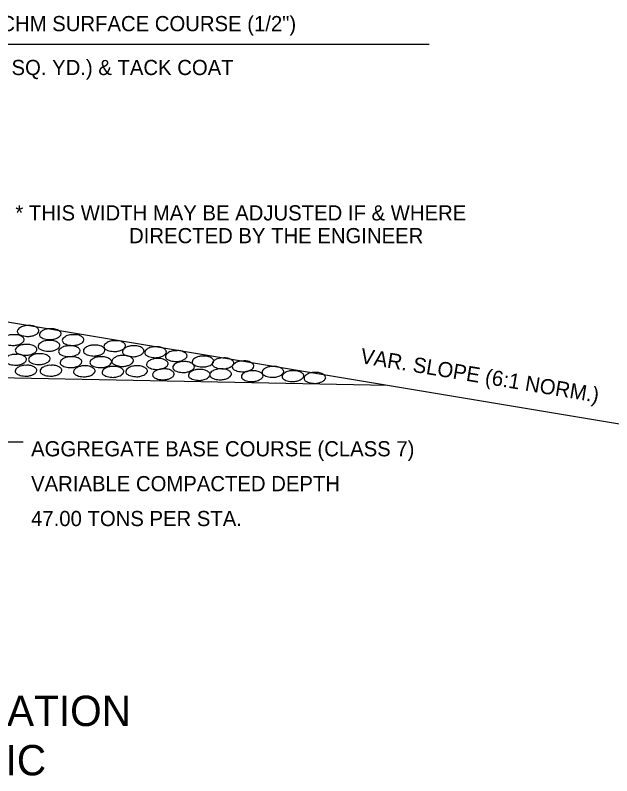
# Model space of a CAD drawing. Extents: x 1931522 to 1935523, y 600380 to 605075.
# Drawn here: x 1933516.8 to 1933752.7, y 604149.7 to 604450.3 of the extents above; entities that cross this region are included whole.
import ezdxf

# ---------------------------------------------------------------- set-up
doc = ezdxf.new("R2010")
doc.units = 0
doc.layers.add('Default', color=7, linetype='Continuous')
doc.layers.add('R_Border', color=7, linetype='Continuous')

msp = doc.modelspace()

# ---------------------------------------------------------------- linework, layer by layer
at = {"layer": 'Default'}
for p, q in [((1933680.47, 604438.7), (1933439.73, 604438.7)), ((1933439.73, 604341.45), (1933830.96, 604276.24)), ((1933261.14, 604312.09), (1933664.05, 604304.05))]:
    msp.add_line(p, q, dxfattribs=at)
for points in [[(1933521.88, 604327.61), (1933523.38, 604327.58), (1933525.22, 604326.96), (1933526.08, 604326.1), (1933526.22, 604325.59), (1933525.75, 604324.65), (1933525.23, 604324.25), (1933524.24, 604323.75), (1933522.77, 604323.41), (1933522.01, 604323.31), (1933520.9, 604323.44), (1933519.64, 604323.64), (1933518.69, 604324.03), (1933517.8, 604324.72), (1933517.66, 604325.32), (1933517.96, 604326.15), (1933518.64, 604326.69), (1933519.27, 604327.13), (1933520.26, 604327.43), (1933520.92, 604327.58), (1933521.88, 604327.61)], [(1933530.61, 604326.34), (1933532.12, 604326.32), (1933533.96, 604325.71), (1933534.85, 604324.84), (1933534.97, 604324.33), (1933534.49, 604323.41), (1933533.98, 604323), (1933533, 604322.52), (1933531.51, 604322.16), (1933530.75, 604322.07), (1933529.64, 604322.18), (1933528.43, 604322.38), (1933527.43, 604322.77), (1933526.58, 604323.47), (1933526.43, 604324.06), (1933526.72, 604324.89), (1933527.39, 604325.42), (1933528.02, 604325.87), (1933529.02, 604326.18), (1933529.66, 604326.32), (1933530.61, 604326.34)], [(1933515.99, 604324.03), (1933517.51, 604324), (1933519.34, 604323.39), (1933520.23, 604322.52), (1933520.36, 604322.02), (1933519.87, 604321.07), (1933519.36, 604320.68), (1933518.38, 604320.18), (1933516.9, 604319.84), (1933516.15, 604319.76), (1933515.03, 604319.85), (1933513.8, 604320.07), (1933512.83, 604320.45), (1933511.94, 604321.15), (1933511.82, 604321.74), (1933512.07, 604322.57), (1933512.77, 604323.1), (1933513.41, 604323.53), (1933514.4, 604323.87), (1933515.06, 604324), (1933515.99, 604324.03)], [(1933539.63, 604324.03), (1933541.13, 604324), (1933542.95, 604323.39), (1933543.87, 604322.52), (1933543.98, 604322.02), (1933543.53, 604321.07), (1933543, 604320.68), (1933542.02, 604320.18), (1933540.54, 604319.84), (1933539.77, 604319.76), (1933538.64, 604319.85), (1933537.41, 604320.07), (1933536.47, 604320.45), (1933535.6, 604321.15), (1933535.44, 604321.74), (1933535.71, 604322.57), (1933536.41, 604323.1), (1933537.03, 604323.53), (1933538.06, 604323.87), (1933538.7, 604324), (1933539.63, 604324.03)], [(1933521.07, 604320.18), (1933522.59, 604320.15), (1933524.39, 604319.54), (1933525.28, 604318.67), (1933525.42, 604318.2), (1933524.92, 604317.25), (1933524.41, 604316.85), (1933523.44, 604316.36), (1933521.95, 604315.99), (1933521.2, 604315.93), (1933520.09, 604316), (1933518.86, 604316.21), (1933517.9, 604316.6), (1933517.01, 604317.3), (1933516.85, 604317.91), (1933517.15, 604318.73), (1933517.83, 604319.29), (1933518.47, 604319.7), (1933519.45, 604320.01), (1933520.11, 604320.15), (1933521.07, 604320.18)], [(1933530.13, 604321.74), (1933531.64, 604321.72), (1933533.45, 604321.12), (1933534.35, 604320.26), (1933534.48, 604319.74), (1933533.99, 604318.78), (1933533.49, 604318.4), (1933532.51, 604317.91), (1933531.03, 604317.53), (1933530.27, 604317.47), (1933529.16, 604317.58), (1933527.92, 604317.78), (1933526.95, 604318.17), (1933526.06, 604318.86), (1933525.92, 604319.46), (1933526.2, 604320.29), (1933526.9, 604320.82), (1933527.53, 604321.24), (1933528.52, 604321.58), (1933529.18, 604321.72), (1933530.13, 604321.74)], [(1933556.12, 604321.65), (1933557.63, 604321.63), (1933559.46, 604321.01), (1933560.34, 604320.13), (1933560.48, 604319.64), (1933559.99, 604318.72), (1933559.47, 604318.28), (1933558.47, 604317.81), (1933556.99, 604317.45), (1933556.25, 604317.38), (1933555.14, 604317.47), (1933553.89, 604317.67), (1933552.94, 604318.06), (1933552.05, 604318.76), (1933551.91, 604319.36), (1933552.19, 604320.18), (1933552.86, 604320.73), (1933553.52, 604321.18), (1933554.52, 604321.49), (1933555.17, 604321.63), (1933556.12, 604321.65)], [(1933538.2, 604319.64), (1933539.73, 604319.6), (1933541.52, 604319), (1933542.42, 604318.11), (1933542.56, 604317.63), (1933542.08, 604316.69), (1933541.53, 604316.27), (1933540.58, 604315.8), (1933539.07, 604315.43), (1933538.34, 604315.37), (1933537.22, 604315.46), (1933536, 604315.69), (1933535.04, 604316.04), (1933534.15, 604316.75), (1933533.99, 604317.36), (1933534.27, 604318.2), (1933534.96, 604318.73), (1933535.61, 604319.15), (1933536.63, 604319.48), (1933537.23, 604319.6), (1933538.2, 604319.64)], [(1933547.97, 604319.87), (1933549.51, 604319.85), (1933551.32, 604319.23), (1933552.21, 604318.37), (1933552.32, 604317.86), (1933551.85, 604316.92), (1933551.34, 604316.52), (1933550.37, 604316.02), (1933548.87, 604315.69), (1933548.13, 604315.58), (1933547, 604315.71), (1933545.79, 604315.91), (1933544.82, 604316.27), (1933543.93, 604317), (1933543.78, 604317.59), (1933544.06, 604318.42), (1933544.74, 604318.95), (1933545.4, 604319.39), (1933546.38, 604319.7), (1933547.02, 604319.85), (1933547.97, 604319.87)], [(1933563.41, 604319.59), (1933564.92, 604319.57), (1933566.75, 604318.95), (1933567.64, 604318.08), (1933567.76, 604317.59), (1933567.28, 604316.66), (1933566.76, 604316.22), (1933565.78, 604315.76), (1933564.3, 604315.38), (1933563.55, 604315.33), (1933562.43, 604315.41), (1933561.2, 604315.63), (1933560.22, 604316), (1933559.35, 604316.71), (1933559.22, 604317.3), (1933559.49, 604318.11), (1933560.17, 604318.67), (1933560.83, 604319.12), (1933561.81, 604319.43), (1933562.45, 604319.57), (1933563.41, 604319.59)], [(1933572.23, 604319.18), (1933573.74, 604319.17), (1933575.57, 604318.56), (1933576.46, 604317.7), (1933576.6, 604317.2), (1933576.13, 604316.24), (1933575.58, 604315.83), (1933574.62, 604315.37), (1933573.15, 604315.01), (1933572.37, 604314.95), (1933571.27, 604315.02), (1933570.02, 604315.23), (1933569.07, 604315.63), (1933568.2, 604316.35), (1933568.04, 604316.92), (1933568.29, 604317.75), (1933569.01, 604318.28), (1933569.63, 604318.73), (1933570.66, 604319.04), (1933571.3, 604319.17), (1933572.23, 604319.18)], [(1933580.4, 604317.7), (1933581.91, 604317.69), (1933583.73, 604317.05), (1933584.65, 604316.19), (1933584.79, 604315.69), (1933584.29, 604314.76), (1933583.76, 604314.34), (1933582.8, 604313.85), (1933581.29, 604313.48), (1933580.55, 604313.43), (1933579.42, 604313.51), (1933578.2, 604313.73), (1933577.25, 604314.12), (1933576.36, 604314.82), (1933576.22, 604315.44), (1933576.49, 604316.22), (1933577.17, 604316.78), (1933577.83, 604317.22), (1933578.81, 604317.55), (1933579.43, 604317.69), (1933580.4, 604317.7)], [(1933516.93, 604316.25), (1933518.44, 604316.24), (1933520.26, 604315.6), (1933521.18, 604314.74), (1933521.32, 604314.24), (1933520.82, 604313.31), (1933520.3, 604312.89), (1933519.33, 604312.41), (1933517.82, 604312.03), (1933517.09, 604311.98), (1933515.95, 604312.06), (1933514.73, 604312.28), (1933513.78, 604312.67), (1933512.89, 604313.37), (1933512.75, 604313.99), (1933513.02, 604314.77), (1933513.7, 604315.33), (1933514.36, 604315.77), (1933515.34, 604316.1), (1933515.96, 604316.24), (1933516.93, 604316.25)], [(1933526.29, 604316.49), (1933527.81, 604316.47), (1933529.63, 604315.83), (1933530.55, 604314.98), (1933530.69, 604314.48), (1933530.19, 604313.54), (1933529.66, 604313.12), (1933528.69, 604312.64), (1933527.18, 604312.26), (1933526.45, 604312.22), (1933525.31, 604312.3), (1933524.1, 604312.51), (1933523.15, 604312.9), (1933522.26, 604313.61), (1933522.12, 604314.23), (1933522.38, 604315.01), (1933523.07, 604315.57), (1933523.72, 604316), (1933524.71, 604316.33), (1933525.33, 604316.47), (1933526.29, 604316.49)], [(1933538.79, 604315.29), (1933540.3, 604315.27), (1933542.13, 604314.63), (1933543.05, 604313.78), (1933543.19, 604313.28), (1933542.69, 604312.34), (1933542.16, 604311.92), (1933541.19, 604311.44), (1933539.68, 604311.07), (1933538.95, 604311.02), (1933537.81, 604311.1), (1933536.59, 604311.31), (1933535.64, 604311.7), (1933534.76, 604312.41), (1933534.62, 604313.03), (1933534.88, 604313.81), (1933535.57, 604314.37), (1933536.22, 604314.8), (1933537.2, 604315.13), (1933537.83, 604315.27), (1933538.79, 604315.29)], [(1933550.57, 604315.29), (1933552.08, 604315.27), (1933553.91, 604314.63), (1933554.83, 604313.78), (1933554.97, 604313.28), (1933554.47, 604312.34), (1933553.94, 604311.92), (1933552.97, 604311.44), (1933551.46, 604311.07), (1933550.73, 604311.02), (1933549.59, 604311.1), (1933548.38, 604311.31), (1933547.43, 604311.7), (1933546.54, 604312.41), (1933546.4, 604313.03), (1933546.66, 604313.81), (1933547.35, 604314.37), (1933548, 604314.8), (1933548.98, 604315.13), (1933549.61, 604315.27), (1933550.57, 604315.29)], [(1933559.24, 604315.77), (1933560.75, 604315.76), (1933562.57, 604315.12), (1933563.49, 604314.26), (1933563.63, 604313.76), (1933563.13, 604312.83), (1933562.6, 604312.41), (1933561.64, 604311.92), (1933560.13, 604311.55), (1933559.39, 604311.5), (1933558.26, 604311.58), (1933557.04, 604311.8), (1933556.09, 604312.19), (1933555.2, 604312.89), (1933555.06, 604313.51), (1933555.33, 604314.29), (1933556.01, 604314.85), (1933556.67, 604315.29), (1933557.65, 604315.62), (1933558.27, 604315.76), (1933559.24, 604315.77)], [(1933572.95, 604314.57), (1933574.46, 604314.56), (1933576.28, 604313.92), (1933577.2, 604313.06), (1933577.34, 604312.56), (1933576.85, 604311.63), (1933576.32, 604311.21), (1933575.35, 604310.72), (1933573.84, 604310.35), (1933573.11, 604310.3), (1933571.97, 604310.38), (1933570.75, 604310.6), (1933569.8, 604310.99), (1933568.91, 604311.69), (1933568.77, 604312.31), (1933569.04, 604313.09), (1933569.72, 604313.65), (1933570.38, 604314.09), (1933571.36, 604314.42), (1933571.98, 604314.56), (1933572.95, 604314.57)], [(1933590.98, 604315.54), (1933592.49, 604315.52), (1933594.31, 604314.88), (1933595.23, 604314.03), (1933595.37, 604313.53), (1933594.88, 604312.59), (1933594.35, 604312.17), (1933593.38, 604311.69), (1933591.87, 604311.31), (1933591.14, 604311.27), (1933590, 604311.35), (1933588.78, 604311.56), (1933587.83, 604311.95), (1933586.94, 604312.65), (1933586.8, 604313.28), (1933587.07, 604314.06), (1933587.75, 604314.62), (1933588.41, 604315.05), (1933589.39, 604315.38), (1933590.01, 604315.52), (1933590.98, 604315.54)], [(1933598.91, 604314.82), (1933600.42, 604314.8), (1933602.25, 604314.17), (1933603.17, 604313.31), (1933603.31, 604312.81), (1933602.81, 604311.88), (1933602.28, 604311.45), (1933601.31, 604310.97), (1933599.8, 604310.6), (1933599.07, 604310.55), (1933597.93, 604310.63), (1933596.71, 604310.85), (1933595.76, 604311.24), (1933594.88, 604311.94), (1933594.74, 604312.56), (1933595, 604313.34), (1933595.69, 604313.9), (1933596.34, 604314.34), (1933597.32, 604314.66), (1933597.95, 604314.8), (1933598.91, 604314.82)], [(1933521.01, 604311.92), (1933522.52, 604311.91), (1933524.35, 604311.27), (1933525.27, 604310.41), (1933525.41, 604309.91), (1933524.91, 604308.98), (1933524.38, 604308.56), (1933523.41, 604308.07), (1933521.9, 604307.7), (1933521.17, 604307.65), (1933520.03, 604307.73), (1933518.81, 604307.95), (1933517.86, 604308.34), (1933516.98, 604309.04), (1933516.84, 604309.66), (1933517.1, 604310.44), (1933517.79, 604311), (1933518.44, 604311.44), (1933519.42, 604311.77), (1933520.05, 604311.91), (1933521.01, 604311.92)], [(1933530.86, 604311.92), (1933532.37, 604311.91), (1933534.2, 604311.27), (1933535.11, 604310.41), (1933535.25, 604309.91), (1933534.76, 604308.98), (1933534.23, 604308.56), (1933533.26, 604308.07), (1933531.75, 604307.7), (1933531.02, 604307.65), (1933529.88, 604307.73), (1933528.66, 604307.95), (1933527.71, 604308.34), (1933526.82, 604309.04), (1933526.68, 604309.66), (1933526.95, 604310.44), (1933527.63, 604311), (1933528.29, 604311.44), (1933529.27, 604311.77), (1933529.89, 604311.91), (1933530.86, 604311.92)], [(1933544.07, 604311.67), (1933545.59, 604311.66), (1933547.41, 604311.02), (1933548.33, 604310.16), (1933548.47, 604309.66), (1933547.97, 604308.73), (1933547.44, 604308.31), (1933546.47, 604307.82), (1933544.96, 604307.45), (1933544.23, 604307.4), (1933543.09, 604307.48), (1933541.88, 604307.7), (1933540.93, 604308.09), (1933540.04, 604308.79), (1933539.9, 604309.41), (1933540.16, 604310.19), (1933540.85, 604310.75), (1933541.5, 604311.19), (1933542.49, 604311.52), (1933543.11, 604311.66), (1933544.07, 604311.67)], [(1933555.39, 604311.44), (1933556.9, 604311.42), (1933558.72, 604310.78), (1933559.64, 604309.93), (1933559.78, 604309.43), (1933559.28, 604308.49), (1933558.75, 604308.07), (1933557.79, 604307.59), (1933556.28, 604307.22), (1933555.54, 604307.17), (1933554.41, 604307.25), (1933553.19, 604307.47), (1933552.24, 604307.85), (1933551.35, 604308.56), (1933551.21, 604309.18), (1933551.48, 604309.96), (1933552.16, 604310.52), (1933552.82, 604310.96), (1933553.8, 604311.28), (1933554.42, 604311.42), (1933555.39, 604311.44)], [(1933564.77, 604311.69), (1933566.28, 604311.67), (1933568.1, 604311.03), (1933569.02, 604310.18), (1933569.16, 604309.68), (1933568.66, 604308.74), (1933568.13, 604308.32), (1933567.17, 604307.84), (1933565.66, 604307.47), (1933564.92, 604307.42), (1933563.79, 604307.5), (1933562.57, 604307.71), (1933561.62, 604308.1), (1933560.73, 604308.81), (1933560.59, 604309.43), (1933560.86, 604310.21), (1933561.54, 604310.77), (1933562.2, 604311.21), (1933563.18, 604311.53), (1933563.8, 604311.67), (1933564.77, 604311.69)], [(1933583.28, 604313.37), (1933584.79, 604313.36), (1933586.62, 604312.72), (1933587.54, 604311.86), (1933587.68, 604311.36), (1933587.18, 604310.43), (1933586.65, 604310.01), (1933585.68, 604309.52), (1933584.17, 604309.15), (1933583.44, 604309.1), (1933582.3, 604309.18), (1933581.08, 604309.4), (1933580.13, 604309.79), (1933579.25, 604310.49), (1933579.11, 604311.11), (1933579.37, 604311.89), (1933580.06, 604312.45), (1933580.71, 604312.89), (1933581.69, 604313.22), (1933582.32, 604313.36), (1933583.28, 604313.37)], [(1933606.84, 604313.62), (1933608.35, 604313.61), (1933610.18, 604312.97), (1933611.1, 604312.11), (1933611.24, 604311.61), (1933610.74, 604310.68), (1933610.21, 604310.25), (1933609.24, 604309.77), (1933607.73, 604309.4), (1933607, 604309.35), (1933605.86, 604309.43), (1933604.65, 604309.65), (1933603.7, 604310.04), (1933602.81, 604310.74), (1933602.67, 604311.36), (1933602.93, 604312.14), (1933603.62, 604312.7), (1933604.27, 604313.14), (1933605.25, 604313.46), (1933605.88, 604313.61), (1933606.84, 604313.62)], [(1933618.62, 604311.45), (1933620.14, 604311.44), (1933621.96, 604310.8), (1933622.88, 604309.94), (1933623.02, 604309.44), (1933622.52, 604308.51), (1933621.99, 604308.09), (1933621.02, 604307.61), (1933619.51, 604307.23), (1933618.78, 604307.18), (1933617.64, 604307.26), (1933616.43, 604307.48), (1933615.48, 604307.87), (1933614.59, 604308.57), (1933614.45, 604309.2), (1933614.71, 604309.97), (1933615.4, 604310.54), (1933616.05, 604310.97), (1933617.03, 604311.3), (1933617.66, 604311.44), (1933618.62, 604311.45)], [(1933575.35, 604310.49), (1933576.86, 604310.47), (1933578.68, 604309.83), (1933579.6, 604308.98), (1933579.74, 604308.48), (1933579.25, 604307.54), (1933578.72, 604307.12), (1933577.75, 604306.64), (1933576.24, 604306.27), (1933575.51, 604306.22), (1933574.37, 604306.3), (1933573.15, 604306.51), (1933572.2, 604306.9), (1933571.31, 604307.61), (1933571.17, 604308.23), (1933571.44, 604309.01), (1933572.12, 604309.57), (1933572.78, 604310.01), (1933573.76, 604310.33), (1933574.38, 604310.47), (1933575.35, 604310.49)], [(1933589.53, 604310.24), (1933591.04, 604310.22), (1933592.87, 604309.58), (1933593.78, 604308.73), (1933593.92, 604308.23), (1933593.43, 604307.29), (1933592.9, 604306.87), (1933591.93, 604306.39), (1933590.42, 604306.02), (1933589.69, 604305.97), (1933588.55, 604306.05), (1933587.33, 604306.27), (1933586.38, 604306.66), (1933585.49, 604307.36), (1933585.35, 604307.98), (1933585.62, 604308.76), (1933586.3, 604309.32), (1933586.96, 604309.76), (1933587.94, 604310.08), (1933588.56, 604310.22), (1933589.53, 604310.24)], [(1933597.95, 604310.49), (1933599.46, 604310.47), (1933601.28, 604309.83), (1933602.2, 604308.98), (1933602.34, 604308.48), (1933601.84, 604307.54), (1933601.31, 604307.12), (1933600.35, 604306.64), (1933598.83, 604306.27), (1933598.1, 604306.22), (1933596.96, 604306.3), (1933595.75, 604306.51), (1933594.8, 604306.9), (1933593.91, 604307.61), (1933593.77, 604308.23), (1933594.03, 604309.01), (1933594.72, 604309.57), (1933595.37, 604310.01), (1933596.36, 604310.33), (1933596.98, 604310.47), (1933597.95, 604310.49)], [(1933610.44, 604309.77), (1933611.95, 604309.76), (1933613.78, 604309.12), (1933614.7, 604308.26), (1933614.84, 604307.76), (1933614.34, 604306.83), (1933613.81, 604306.41), (1933612.84, 604305.92), (1933611.33, 604305.55), (1933610.6, 604305.5), (1933609.46, 604305.58), (1933608.25, 604305.8), (1933607.3, 604306.19), (1933606.41, 604306.89), (1933606.27, 604307.51), (1933606.53, 604308.29), (1933607.22, 604308.85), (1933607.87, 604309.29), (1933608.85, 604309.62), (1933609.48, 604309.76), (1933610.44, 604309.77)], [(1933626.56, 604309.77), (1933628.07, 604309.76), (1933629.89, 604309.12), (1933630.81, 604308.26), (1933630.95, 604307.76), (1933630.45, 604306.83), (1933629.92, 604306.41), (1933628.96, 604305.92), (1933627.44, 604305.55), (1933626.71, 604305.5), (1933625.57, 604305.58), (1933624.36, 604305.8), (1933623.41, 604306.19), (1933622.52, 604306.89), (1933622.38, 604307.51), (1933622.64, 604308.29), (1933623.33, 604308.85), (1933623.98, 604309.29), (1933624.97, 604309.62), (1933625.59, 604309.76), (1933626.56, 604309.77)], [(1933635.2, 604309.05), (1933636.72, 604309.04), (1933638.54, 604308.4), (1933639.46, 604307.54), (1933639.6, 604307.04), (1933639.1, 604306.11), (1933638.57, 604305.69), (1933637.6, 604305.21), (1933636.09, 604304.83), (1933635.36, 604304.79), (1933634.22, 604304.86), (1933633.01, 604305.08), (1933632.06, 604305.47), (1933631.17, 604306.17), (1933631.03, 604306.8), (1933631.29, 604307.57), (1933631.98, 604308.14), (1933632.63, 604308.57), (1933633.61, 604308.9), (1933634.24, 604309.04), (1933635.2, 604309.05)]]:
    msp.add_spline(points, degree=3, dxfattribs=at)
at = {"layer": 'R_Border'}
msp.add_lwpolyline([(1933458.52, 604307.54), (1933496.22, 604281.68), (1933519.97, 604281.68)], dxfattribs=at)

# ---------------------------------------------------------------- texts
at = {"layer": 'Default'}
for s, height, p in [('VAR. WIDTH ACHM SURFACE COURSE (1/2")', 6, (1933456.13, 604444.02)), ('(220 LBS. PER SQ. YD.) & TACK COAT', 6, (1933458.73, 604426.68)), ('* THIS WIDTH MAY BE ADJUSTED IF & WHERE ', 6, (1933516.88, 604369.2)), ('DIRECTED BY THE ENGINEER', 6, (1933561.85, 604360.2)), ('AGGREGATE BASE COURSE (CLASS 7)', 6, (1933523.1, 604275.94)), ('VARIABLE COMPACTED DEPTH', 6, (1933523.1, 604262.15)), ('47.00 TONS PER STA.', 6, (1933523.1, 604248.36)), ('TRENCHING & SHOULDER PREPARATION', 12, (1933238.96, 604169.32)), ('FOR MAINTENANCE OF TRAFFIC', 12, (1933274.99, 604149.82))]:
    msp.add_text(s, height=height, dxfattribs=at).set_placement(p)
msp.add_text('VAR. SLOPE (6:1 NORM.)', height=6, rotation=350.5384, dxfattribs=at).set_placement((1933653.05, 604312.84))

doc.saveas('drawing.dxf')
